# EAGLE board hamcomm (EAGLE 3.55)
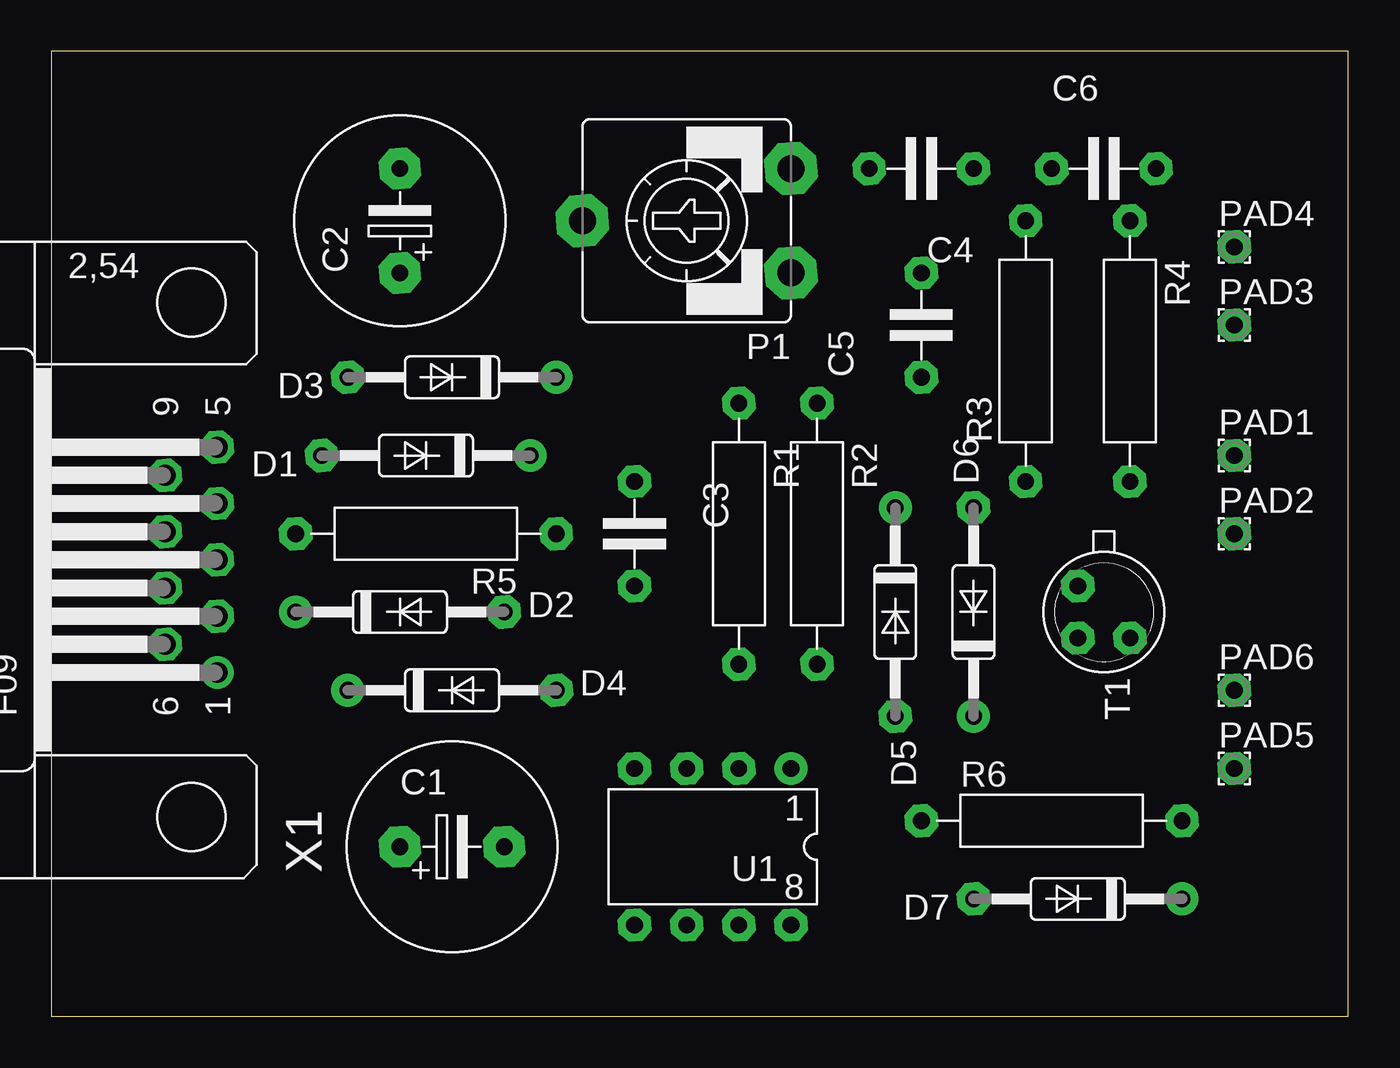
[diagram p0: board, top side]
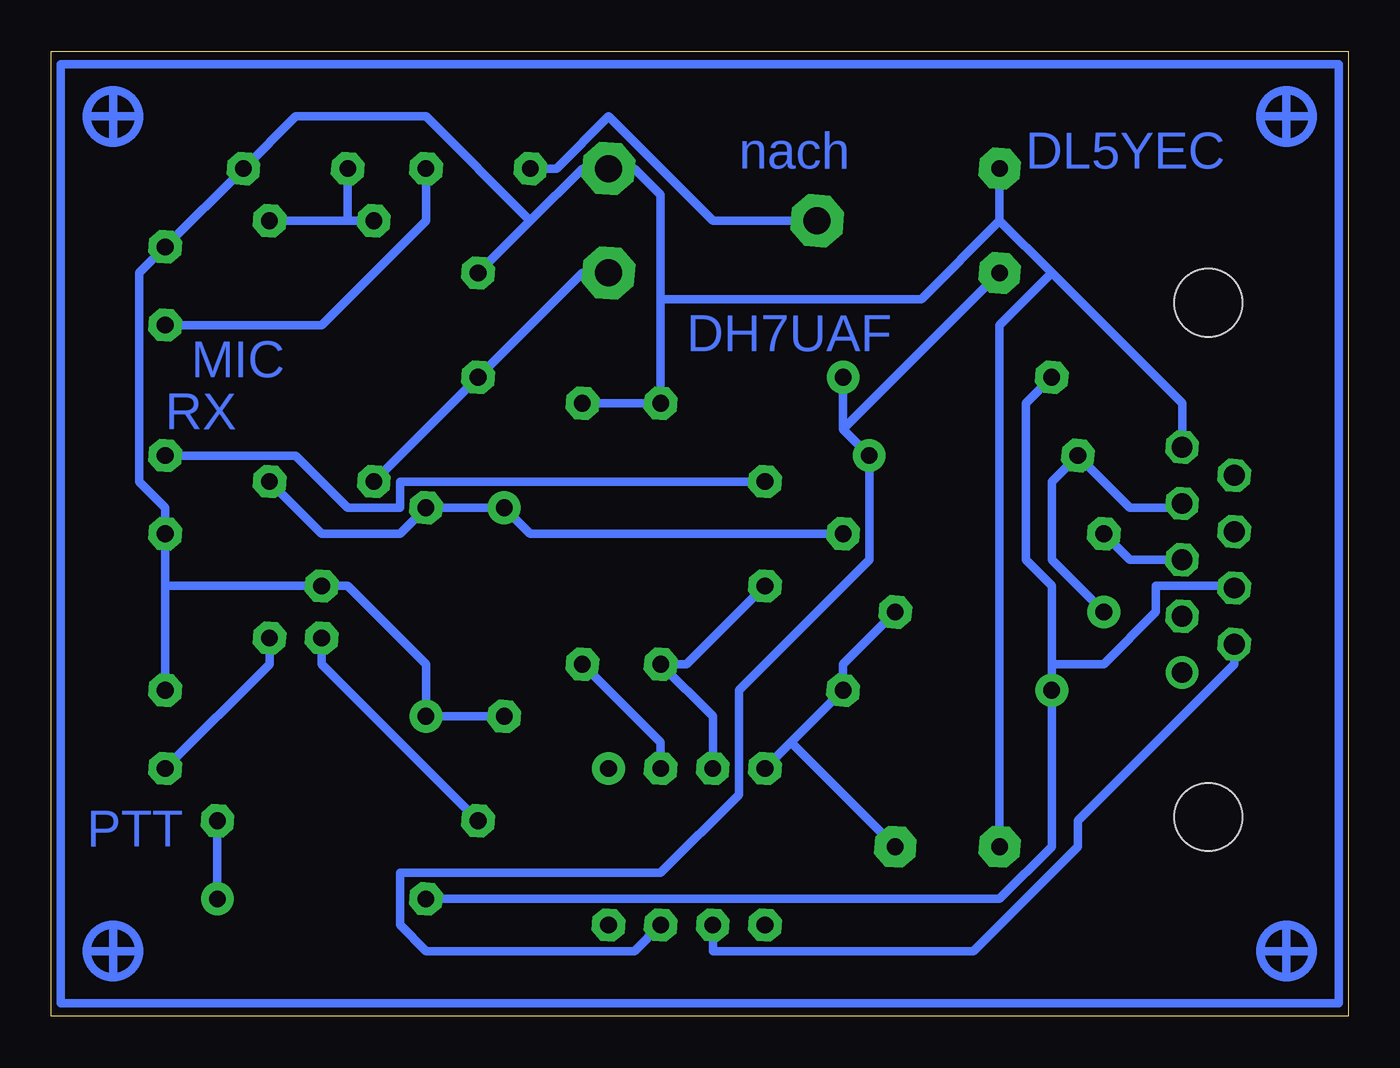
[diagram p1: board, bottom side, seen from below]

Size 63.17 x 46.98 mm. Coordinates in mm from the lower left corner, seen from the top.
Outline: 0,0 63.17,0 63.17,46.98 0,46.98 0,0
Copper layers used: Bottom

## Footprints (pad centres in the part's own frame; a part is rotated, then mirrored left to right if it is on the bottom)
-5 = drill 0.813 pad 2.007 octagon:  -2.54,0;  2.54,0
5 = drill 0.813 pad 1.6 octagon:  -2.54,0;  2.54,0
35-10 = drill 0.813 pad 1.6 round:  -5.08,0 | drill 0.813 pad 1.6 octagon:  5.08,0
9V = drill 1.321 pad 2.54 octagon:  0,5.08;  -2.54,-5.08;  2.54,-5.08
6/0,8 = drill 0.813 pad 1.6 octagon:  0,0
12,5 = drill 0.813 pad 1.6 octagon:  -6.35,0;  6.35,0
18 = drill 0.813 pad 1.6 octagon:  -1.27,-1.27;  1.27,-1.27;  1.27,1.27
L08 = drill 0.813 pad 1.6 round:  -3.81,-3.81 | drill 0.813 pad 1.6 octagon:  -1.27,-3.81;  1.27,-3.81;  3.81,-3.81;  3.81,3.81;  1.27,3.81;  -1.27,3.81;  -3.81,3.81
9H = drill 1.016 pad 1.6 round:  -5.486,-1.27 | drill 1.016 pad 1.6 octagon:  -2.743,-1.27;  0,-1.27;  2.743,-1.27;  5.486,-1.27;  -4.115,1.27;  -1.372,1.27;  1.372,1.27;  4.115,1.27 | hole 3.302: -12.522,0; 12.522,0

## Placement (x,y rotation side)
C1  10uF  [-5]  19.52,8.25 0 top
C2  10uF  [-5]  16.98,38.73 90 top
C3  100nF  [5]  28.41,23.49 270 top
C4  100nF  [5]  42.38,41.27 180 top
C5  220nF  [5]  42.38,33.65 90 top
C6  220nF  [5]  51.27,41.27 0 top
D1  1N4148  [35-10]  18.25,27.3 180 top
D2  1N4148  [35-10]  16.98,19.68 0 top
D3  1N4148  [35-10]  19.52,31.11 180 top
D4  1N4148  [35-10]  19.52,15.87 0 top
D5  1N4148  [35-10]  41.11,19.68 270 top
D6  1N4148  [35-10]  44.92,19.68 90 top
D7  1N4148  [35-10]  50,5.71 180 top
P1  10k  [9V]  30.95,38.73 90 top
PAD1  RX  [6/0,8]  57.62,27.3 0 top
PAD2  M  [6/0,8]  57.62,23.49 0 top
PAD3  MIC  [6/0,8]  57.62,33.65 0 top
PAD4  M  [6/0,8]  57.62,37.46 0 top
PAD5  PTT  [6/0,8]  57.62,12.06 0 top
PAD6  M  [6/0,8]  57.62,15.87 0 top
R1  100k  [12,5]  33.49,23.49 270 top
R2  100k  [12,5]  37.3,23.49 270 top
R3  15k  [12,5]  47.46,32.38 90 top
R4  15k  [12,5]  52.54,32.38 270 top
R5  10k  [12,5]  18.25,23.49 180 top
R6  1k  [12,5]  48.73,9.52 0 top
T1  2N2222  [18]  51.27,19.68 270 top
U1  741P  [L08]  32.22,8.25 180 top
X1  F09H  [9H]  6.82,22.22 90 top

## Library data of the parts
C1-C6 R1-R6 = discrete
D1-D7 = diode
P1 = trimpot
PAD1-PAD6 = wirepad
T1 = npn
U1 = linear
X1 = subd

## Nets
N$1: D1. D2. X1.
N$2: C5. P1. R3.
N$3: U1. X1.
N$5: C6. R3. R4.
N$6: C2. D1. D3. U1.
N$7: C1. D2. D4. U1.
N$8: R2. U1.
N$9: C3. R1. U1.
N$10: C1. C2. C5. C6. D5. D6. P1. PAD2. PAD4. PAD6. R1. R2. T1. X1.
N$11: D5. D6. R4. R5.
N$12: C4. P1.
N$14: C3. PAD1.
N$23: R5. X1.
N$24: R6. T1.
N$25: D7. R6.
N$27: PAD5. T1.
N$29: D3. D4. D7. X1.
N$30: C4. PAD3.

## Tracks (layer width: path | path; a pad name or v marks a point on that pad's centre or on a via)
N$1
  Bottom 0.406: 8.09,24.96 8.09,24.76 10.63,24.76 D1. 14.44,26.03 14.44,22.22 11.9,19.68
N$2
  Bottom 0.406: 36.03,36.19 37.3,36.19 42.38,31.11 47.46,26.03
N$3
  Bottom 0.406: 30.95,4.44 30.95,3.17 18.25,3.17 13.17,8.25 13.17,9.52 5.55,17.14 5.55,18.1 5.55,18.41
N$4
  Bottom 0.406: 0.47,46.35 62.7,46.35 62.7,0.63 0.47,0.63 0.47,46.35
N$5
  Bottom 0.406: 48.73,38.73 52.54,38.73 | R3. 48.73,38.73 | 48.73,38.73 48.73,41.27
N$6
  Bottom 0.406: 33.49,4.44 34.76,3.17 44.92,3.17 46.19,4.44 46.19,6.98 33.49,6.98 29.68,10.79 29.68,15.87 23.33,22.22 23.33,27.3 24.6,28.57 | 24.6,28.57 24.6,31.11 | 24.6,28.57 16.98,36.19
N$7
  Bottom 0.406: 27.14,13.33 28.41,12.06 | 27.14,13.33 D4. 24.6,17.14 D2. | C1. 27.14,13.33
N$8
  Bottom 0.406: 33.49,12.06 33.49,13.33 R2.
N$9
  Bottom 0.406: 30.95,12.06 30.95,14.6 R1. 32.22,17.14 C3.
N$10
  Bottom 0.406: 14.44,36.19 16.98,38.73 | 14.44,36.19 8.09,29.84 8.09,27.71 8.09,27.3 | 16.98,38.73 C2. | 16.98,8.25 16.98,33.65 14.44,36.19 | D5. 44.92,14.6 44.92,17.14 48.73,20.95 50,20.95 57.62,20.95 | 57.62,20.95 PAD2. 57.62,24.76 58.89,26.03 58.89,36.19 PAD4. C6. 51.27,43.81 44.92,43.81 39.84,38.73 | 57.62,20.95 PAD6. | 37.3,29.84 33.49,29.84 33.49,34.92 | 39.84,38.73 37.3,41.27 P1. 34.76,41.27 33.49,40 33.49,34.92 | 39.84,38.73 C5. | 16.98,38.73 20.79,34.92 33.49,34.92
N$11
  Bottom 0.406: 24.6,23.49 39.84,23.49 41.11,24.76 D6. 46.19,23.49 50,23.49 R4.
N$12
  Bottom 0.406: C4. 38.57,41.27 36.03,43.81 30.95,38.73 25.87,38.73
N$13
  Bottom 0.406: 3.01,45.08 3.01,42.54
N$14
  Bottom 0.406: 28.41,26.03 46.19,26.03 46.19,24.76 48.73,24.76 51.27,27.3 PAD1.
N$15
  Bottom 0.406: 4.28,43.81 1.74,43.81
N$16
  Bottom 0.406: 61.43,43.81 58.89,43.81
N$17
  Bottom 0.406: 60.16,45.08 60.16,42.54
N$18
  Bottom 0.406: 60.16,4.44 60.16,1.9
N$19
  Bottom 0.406: 61.43,3.17 58.89,3.17
N$20
  Bottom 0.406: 3.01,4.44 3.01,1.9
N$21
  Bottom 0.406: 4.28,3.17 1.74,3.17
N$23
  Bottom 0.406: 8.09,22.22 10.63,22.22 R5.
N$24
  Bottom 0.406: 42.38,9.52 50,17.14 50,18.41
N$25
  Bottom 0.406: 55.08,5.71 R6.
N$27
  Bottom 0.406: PAD5. 52.54,17.14 T1.
N$29
  Bottom 0.406: 14.44,17.14 14.44,20.95 15.71,22.22 15.71,29.84 D3. | 14.44,17.14 14.44,15.87 14.44,8.25 16.98,5.71 D7. | 14.44,17.14 11.9,17.14 9.36,19.68 9.36,20.95 5.55,20.95 5.55,20.85
N$30
  Bottom 0.406: 44.92,41.27 44.92,38.73 50,33.65 PAD3.
(copper drawn outside any net)
  shapes: Bottom circle x4

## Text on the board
Bottom: DL5YEC | nach | DH7UAF | MIC | RX | PTT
